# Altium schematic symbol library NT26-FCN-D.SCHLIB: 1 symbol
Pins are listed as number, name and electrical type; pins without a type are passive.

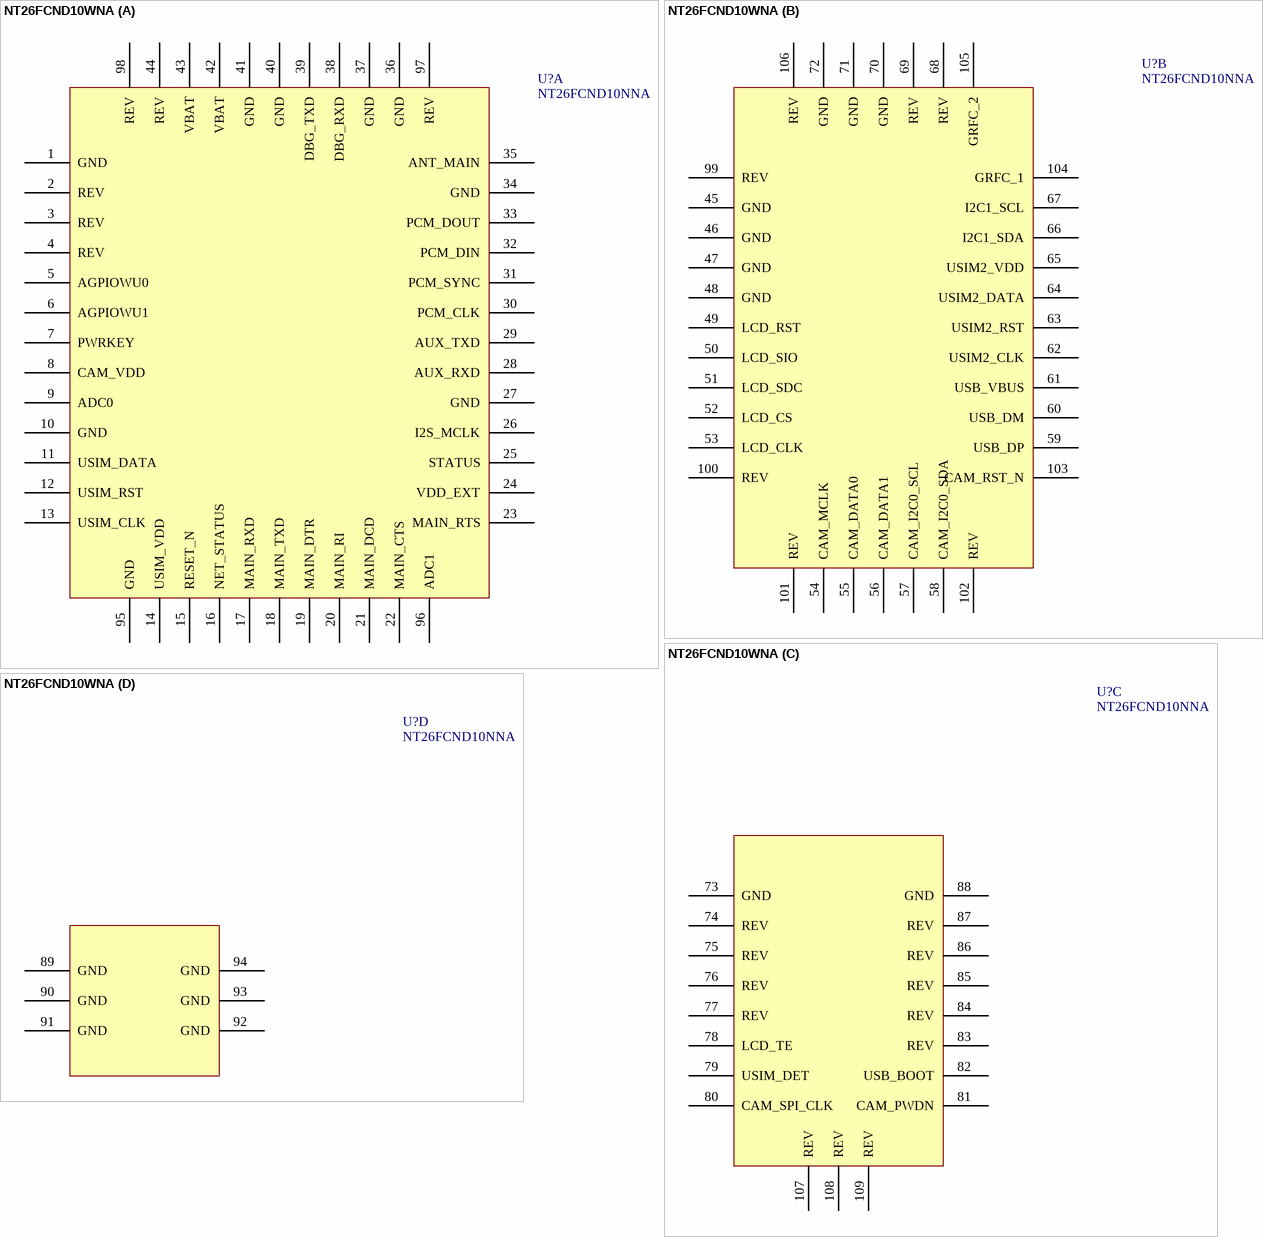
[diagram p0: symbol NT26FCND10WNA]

## NT26FCND10WNA
designator U?, comment NT26FCND10NNA
footprint NT26KCNB0DNNA
part A pins: 1 GND, 2 REV, 3 REV, 4 REV, 5 AGPIOWU0, 6 AGPIOWU1, 7 PWRKEY, 8 CAM_VDD, 9 ADC0, 10 GND, 11 USIM_DATA, 12 USIM_RST, 13 USIM_CLK, 14 USIM_VDD, 15 RESET_N, 16 NET_STATUS, 17 MAIN_RXD, 18 MAIN_TXD, 19 MAIN_DTR, 20 MAIN_RI, 21 MAIN_DCD, 22 MAIN_CTS, 23 MAIN_RTS, 24 VDD_EXT, 25 STATUS, 26 I2S_MCLK, 27 GND, 28 AUX_RXD, 29 AUX_TXD, 30 PCM_CLK, 31 PCM_SYNC, 32 PCM_DIN, 33 PCM_DOUT, 34 GND, 35 ANT_MAIN, 36 GND, 37 GND, 38 DBG_RXD, 39 DBG_TXD, 40 GND, 41 GND, 42 VBAT, 43 VBAT, 44 REV, 95 GND, 96 ADC1, 97 REV, 98 REV
part B pins: 45 GND, 46 GND, 47 GND, 48 GND, 49 LCD_RST, 50 LCD_SIO, 51 LCD_SDC, 52 LCD_CS, 53 LCD_CLK, 54 CAM_MCLK, 55 CAM_DATA0, 56 CAM_DATA1, 57 CAM_I2C0_SCL, 58 CAM_I2C0_SDA, 59 USB_DP, 60 USB_DM, 61 USB_VBUS, 62 USIM2_CLK, 63 USIM2_RST, 64 USIM2_DATA, 65 USIM2_VDD, 66 I2C1_SDA, 67 I2C1_SCL, 68 REV, 69 REV, 70 GND, 71 GND, 72 GND, 99 REV, 100 REV, 101 REV, 102 REV, 103 CAM_RST_N, 104 GRFC_1, 105 GRFC_2, 106 REV
part C pins: 73 GND, 74 REV, 75 REV, 76 REV, 77 REV, 78 LCD_TE, 79 USIM_DET, 80 CAM_SPI_CLK, 81 CAM_PWDN, 82 USB_BOOT, 83 REV, 84 REV, 85 REV, 86 REV, 87 REV, 88 GND, 107 REV, 108 REV, 109 REV
part D pins: 89 GND, 90 GND, 91 GND, 92 GND, 93 GND, 94 GND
